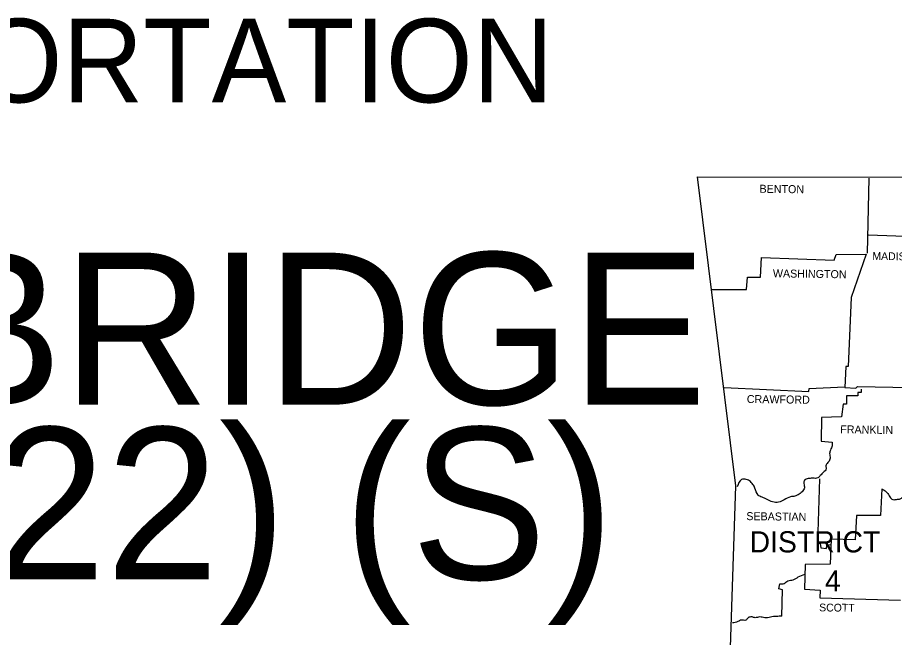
# Model space of a CAD drawing. Extents: x -12863 to 18921, y -8840 to 11152.
# Drawn here: x 7172 to 11783, y 7889 to 11152 of the extents above; entities that cross this region are included whole.
import ezdxf

# ---------------------------------------------------------------- set-up
doc = ezdxf.new("R2010")
doc.units = 0
for name, color, linetype in [('Level 1', 7, 'Continuous'), ('Level 2', 7, 'Continuous'), ('Level 3', 7, 'Continuous')]:
    doc.layers.add(name, color=color, linetype=linetype)

msp = doc.modelspace()

# ---------------------------------------------------------------- linework, layer by layer
at = {"layer": 'Level 1'}
for points in [[(10745.4, 10313), (12327.5, 10312), (13715.8, 10314.9), (15353.7, 10340.4), (16112.9, 10358)], [(10745.4, 10313), (10947.9, 8686.9), (10859.9, 6032.5)], [(11648.5, 10307.1), (11639.7, 9910.9)], [(11646.5, 10007.7), (11887.2, 9999.9), (11893.1, 9968.6), (11926.3, 9967.6), (11925.3, 9948), (11948.8, 9942.2), (11950.8, 9835.5), (11981.1, 9828.7), (11983.1, 9786.6), (12026.1, 9780.7), (12028.1, 9741.6), (12113.2, 9732.8), (12332.4, 9737.7), (12334.3, 10300.3)], [(10822.7, 9721.1), (11005.6, 9720.1), (11010.5, 9784.6), (11078, 9784.6), (11083.9, 9889.3), (11465.5, 9875.6), (11477.2, 9905), (11634.8, 9906), (11555.5, 9679), (11539.9, 9316), (11528.1, 9315), (11522.2, 9205.4), (11580, 9200.5), (11588.8, 9209.3), (12055.5, 9200.5), (12060.4, 9148.7)], [(10887.3, 9204.5), (11332.4, 9183.9), (11334.4, 9199.6), (11520.3, 9208.4)], [(11608.3, 9196.6), (11608.3, 9179), (11589.8, 9179), (11590.7, 9161.4), (11531.1, 9160.4), (11530.1, 9116.4), (11513.4, 9116.4), (11504.6, 9050.8), (11399, 9046), (11398, 8921.7), (11454.7, 8917.8)], [(11388.2, 8724.1), (11378.4, 8387.5), (11393.1, 8383.6), (11396, 8360.1), (11425.4, 8358.1), (11428.3, 8374.8), (11451.8, 8378.7)], [(11716.9, 8671.2), (11710.1, 8531.3), (11582.9, 8530.3), (11576.1, 8403.1), (11449.8, 8406.1), (11445.9, 8275), (11313.8, 8274), (11309.9, 8142.9), (11393.1, 8138), (11390.2, 8097.9), (11814.8, 8086.1)], [(11191.5, 8001), (11194.5, 8139), (11174.9, 8144.8), (11180.8, 8171.3)]]:
    msp.add_lwpolyline(points, dxfattribs=at)
for points in [[(11454.7, 8917.8), (11454.7, 8897.2), (11446.9, 8875.7), (11442, 8857.1), (11445, 8832.7), (11436.1, 8813.1), (11423.4, 8797.4), (11423.4, 8777.9), (11408.8, 8757.3), (11393.1, 8741.7), (11379.4, 8728.9), (11354.9, 8727), (11334.4, 8726), (11313.8, 8719.2), (11306, 8704.5), (11309.9, 8682), (11302.1, 8660.5), (11281.6, 8643.8), (11259.1, 8633.1), (11235.6, 8629.2), (11203.3, 8613.5), (11173.9, 8600.8), (11142.6, 8602.7), (11113.3, 8615.5), (11086.9, 8627.2), (11066.3, 8638.9), (11049.7, 8675.1), (11038.9, 8694.7), (11020.3, 8714.3), (10997.8, 8722.1), (10979.2, 8720.1), (10956.7, 8682)], [(11716.9, 8671.2), (11738.5, 8657.5), (11755.1, 8635), (11769.8, 8616.4), (11794.2, 8615.5), (11813.8, 8619.4), (11836.3, 8638.9)], [(11180.8, 8171.3), (11202.3, 8173.2), (11222.9, 8186.9), (11250.2, 8192.8), (11277.6, 8207.5), (11311.9, 8223.1)], [(11191.5, 8001), (11163.2, 8000), (11130.9, 7996.1), (11101.5, 7992.2), (11075.1, 7997.1), (11050.7, 7993.2), (11034, 7997.1), (11013.5, 7992.2), (11001.7, 7980.5), (10977.3, 7980.5), (10959.7, 7972.6), (10931.3, 7965.8)]]:
    msp.add_spline(points, degree=3, dxfattribs=at)

# ---------------------------------------------------------------- texts
at = {"layer": 'Level 2'}
for s, height, p in [('ARKANSAS DEPARTMENT OF TRANSPORTATION', 440, (-4001.5, 10705.3)), ('DISTRICTS 2, 3, & 7 BRIDGE', 800, (-3530.9, 9114.5)), ('PRESERVATION (2022) (S)', 800, (-3184.4, 8194.8))]:
    msp.add_text(s, height=height, dxfattribs=at).set_placement(p)
for s, height, rotation, p in [('BENTON', 42.07, 359.2527, (11073.2, 10229.8)), ('MADISON', 41.09, 359.0906, (11667, 9876.6)), ('WASHINGTON', 42.06, 359.232, (11143.6, 9784.6)), ('CRAWFORD', 42.06, 359.2771, (11006.6, 9123.2)), ('FRANKLIN', 42.07, 359.1815, (11497.8, 8963.8)), ('SEBASTIAN', 42.06, 359.2816, (11003.7, 8506.8)), ('SCOTT', 41.09, 359.4063, (11387.2, 8026.5))]:
    msp.add_text(s, height=height, rotation=rotation, dxfattribs=at).set_placement(p)
at = {"layer": 'Level 3'}
for s, height, p in [('DISTRICT', 111.54, (11021.3, 8336.6)), ('4', 111.5, (11417.6, 8131.1))]:
    msp.add_text(s, height=height, dxfattribs=at).set_placement(p)

doc.saveas('drawing.dxf')
